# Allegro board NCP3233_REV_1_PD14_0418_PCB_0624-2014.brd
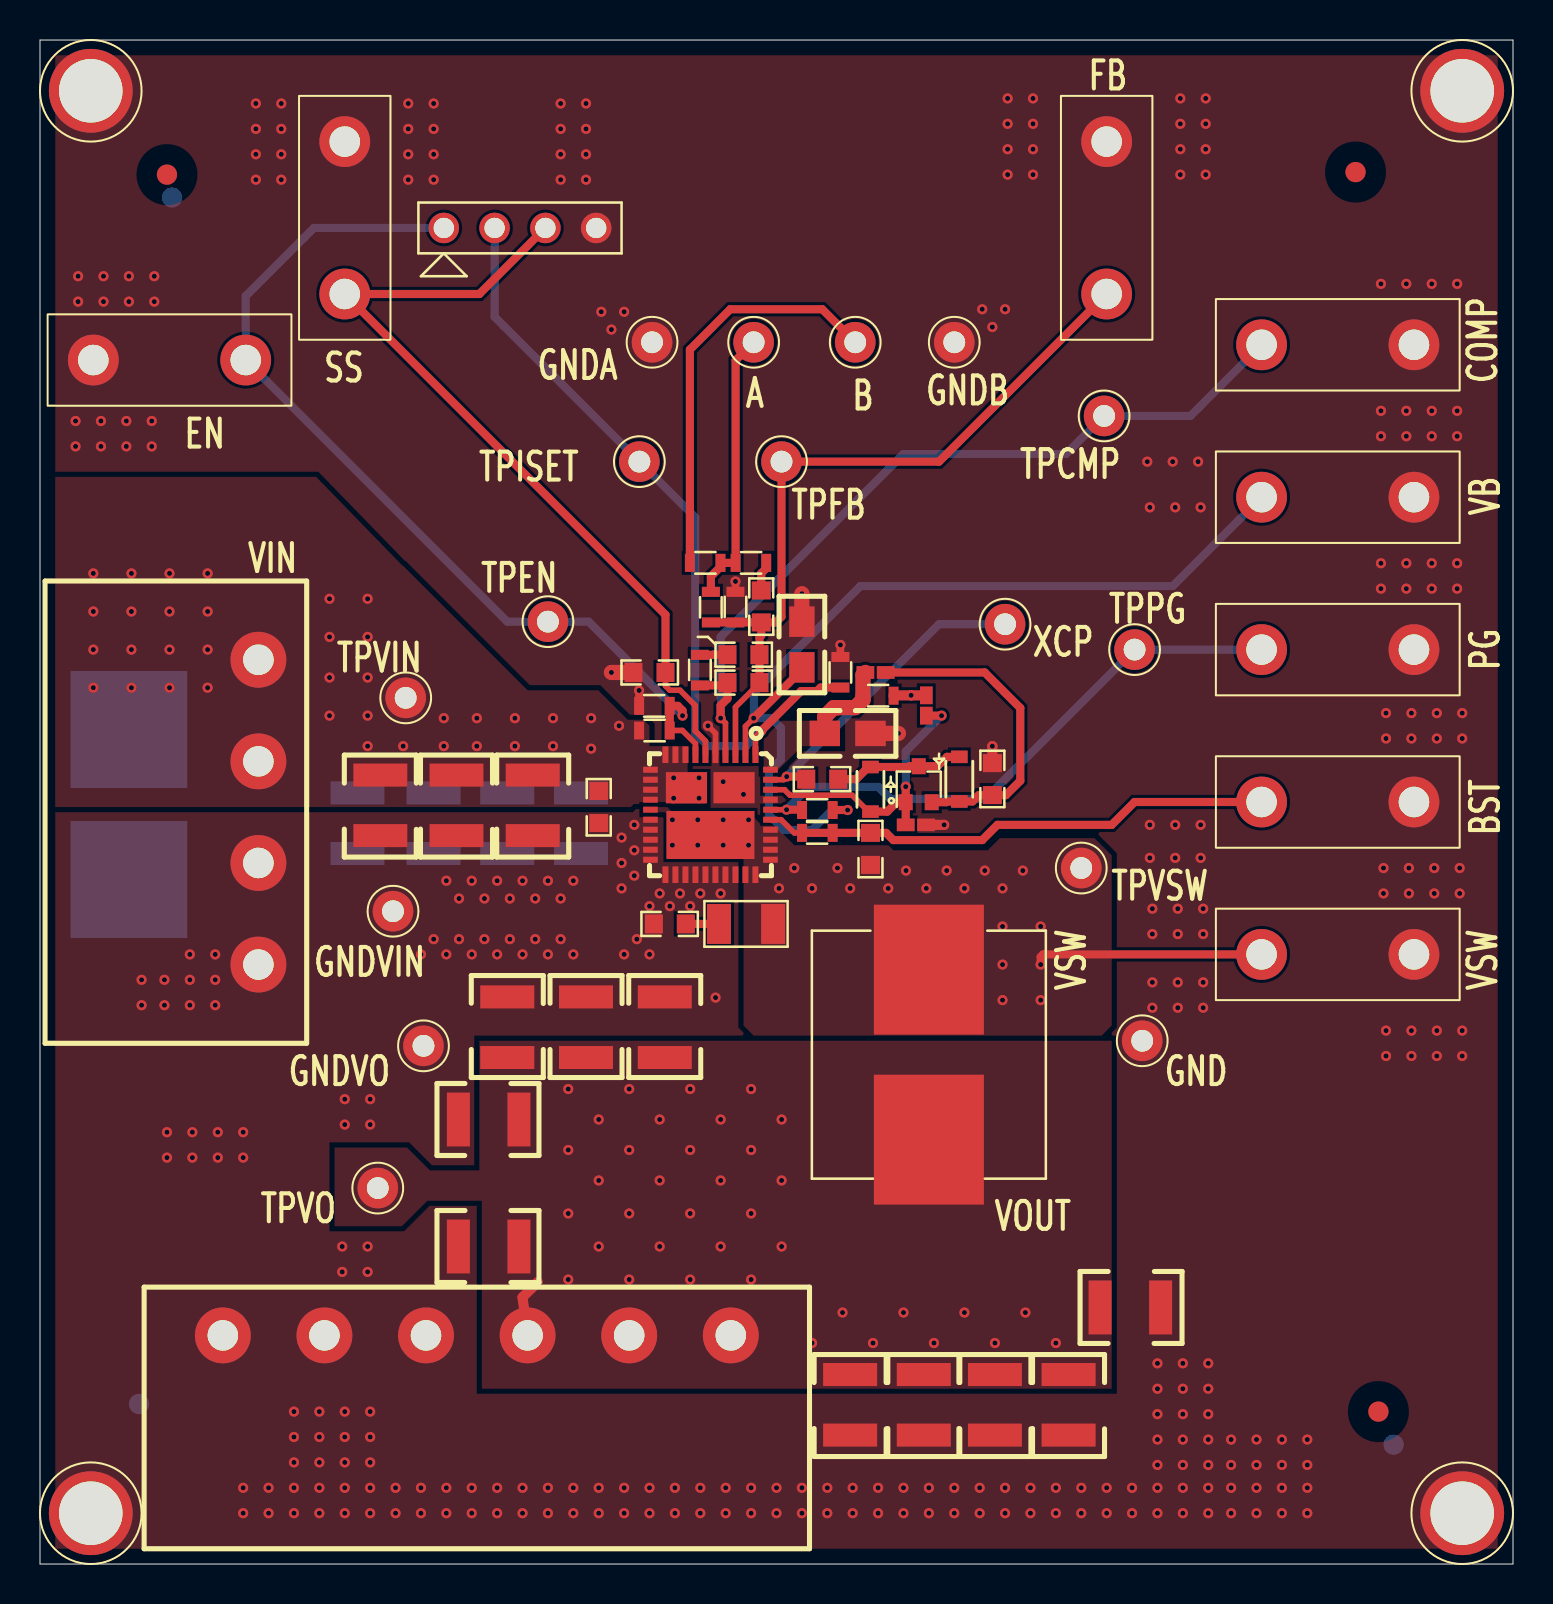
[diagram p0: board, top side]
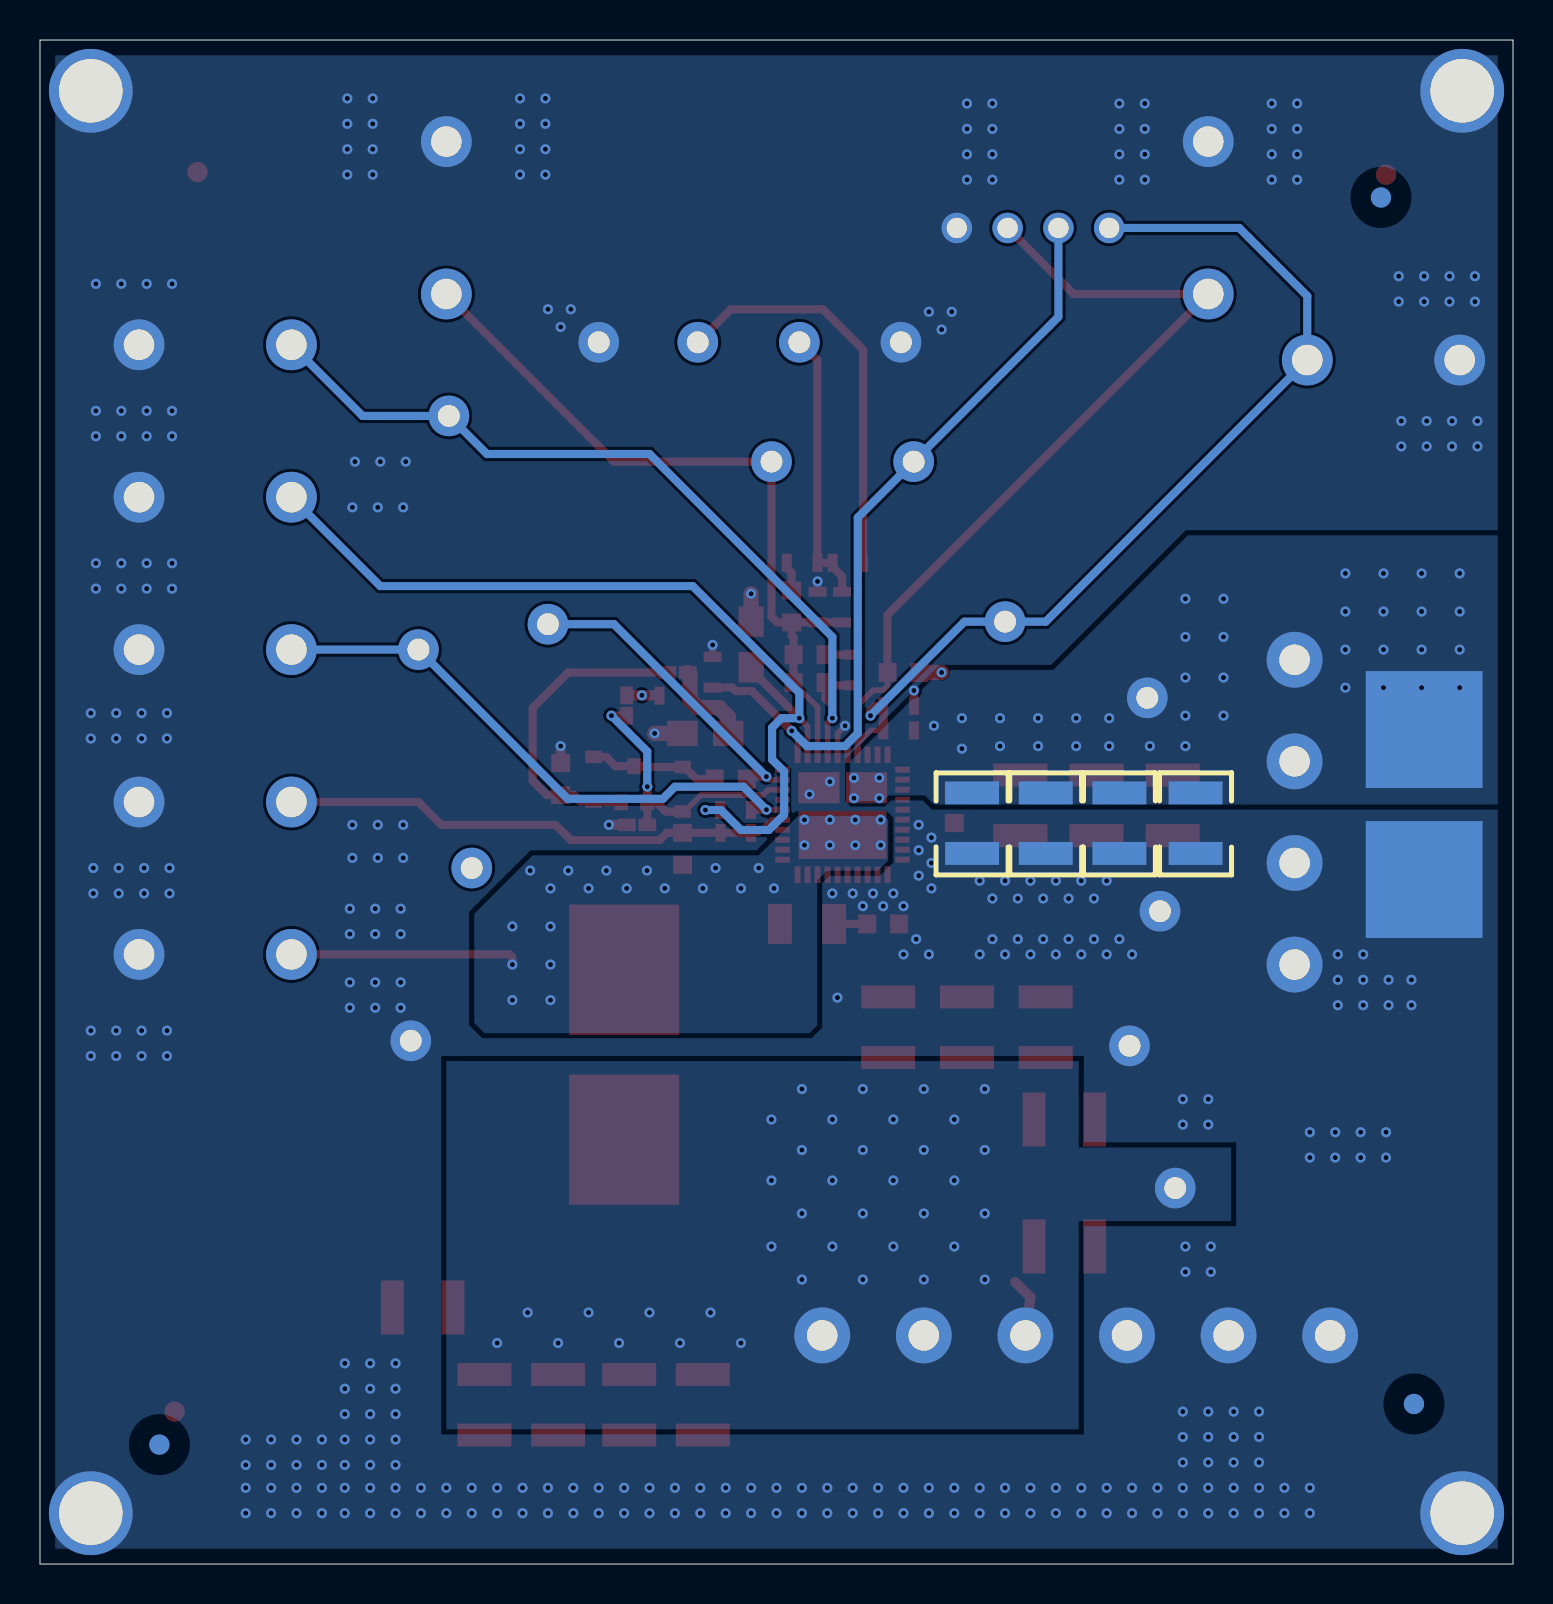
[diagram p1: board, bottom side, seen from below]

Outline 73.66 x 76.2 mm; copper layers: TOP, INNER LAYER 2, INNER LAYER 3, INNER LAYER 4, INNER LAYER 5, BOTTOM. Coordinates in mm from the lower left corner of the outline.
Outline path: 0,76.2 0,0 73.66,0 73.66,76.2 0,76.2

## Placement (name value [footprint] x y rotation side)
C1  22 uF  [C1210]  24.64 37.85 270 top
C2  22 uF  [C1210]  20.83 37.85 270 top
C3  22 uF  [C1210]  17.02 37.85 270 top
C4  22 uF  [C1210]  27.05 36.96 270 bottom
C5  22 uF  [C1210]  23.37 36.96 270 bottom
C6  1 uF  [C0603]  27.94 37.85 270 top
C7  22 uF  [C1210]  19.68 36.96 270 bottom
C8  22 nF  [C0603]  30.48 44.58 0 top
C9  0.1 uF  [C0603]  41.53 35.76 270 top
C10  4.7 uF  [C0805]  38.1 45.97 90 top
C11  1 uF  [C0805]  40.39 41.53 0 top
C13  DNP  [C0603]  31.5 32 180 top
C14  100 uF  [C1210]  31.24 26.92 90 top
C15  100 uF  [C1210]  27.3 26.92 90 top
C16  100 uF  [C1210]  23.37 26.92 90 top
C17  100 uF  [C1210]  22.35 22.23 180 top
C18  100 uF  [C1210]  22.35 15.88 180 top
C19  DNP  [C1210]  40.51 7.87 270 top
C20  DNP  [C1210]  44.2 7.87 270 top
C21  DNP  [C1210]  47.75 7.87 270 top
C22  DNP  [C1210]  51.44 7.87 270 top
C23  DNP  [C1210]  54.61 12.83 0 top
C24  10 pF  [C0603]  35.18 44.07 0 top
C25  2.2 nF  [C0603]  35.18 45.47 0 top
C26  680 pF  [C0603]  36.07 47.88 270 top
C27  22 uF  [C1210]  15.88 36.96 270 bottom
C28  1 uF  [C0603]  39.12 39.24 180 top
C29  1 uF  [C0603]  47.62 39.24 90 top
CBULK1  DNP  [SMD_E]  4.45 37.97 180 bottom
D1  NSR1020MW2  [SOD-323]  41.53 38.73 270 top
D2  NSR1020MW2  [SOD-323]  45.97 39.24 90 top
D3  BAT54SW  [SOT-323]  43.94 38.99 0 top
J1  HEADER 4  [HEADER_4P_200_RA]  10.92 29.97 90 top
J2  HEADER 6  [HEADER_6P_200_RA]  34.54 11.43 180 top
J3  TP_SCOPE  [SCOPE_SOCKET_PIN_300]  64.9 30.48 0 top
J4  TP_SCOPE  [SCOPE_SOCKET_PIN_300]  53.34 67.31 90 top
J7  TP_SCOPE  [SCOPE_SOCKET_PIN_300]  64.9 53.34 0 top
J8  TP_SCOPE  [SCOPE_SOCKET_PIN_300]  6.48 60.2 180 top
J9  TP_SCOPE  [SCOPE_SOCKET_PIN_300]  64.9 38.1 0 top
J11  TP_SCOPE  [SCOPE_SOCKET_PIN_300]  64.9 45.72 0 top
J12  TP_SCOPE  [SCOPE_SOCKET_PIN_300]  64.9 60.96 0 top
J13  TP_SCOPE  [SCOPE_SOCKET_PIN_300]  15.24 67.31 90 top
J14  CON4  [SIP-4]  20.19 66.8 0 top
JP1  SHORT_PIN  [SIG_ISO]  43.8 36.96 90 top
JP2  SHORT_PIN  [SIG_ISO]  44.32 42.93 0 top
JP3  SHORT_PIN  [SIG_ISO]  41.78 44.58 90 top
L1  0.47 uH  [MSS1278]  44.45 29.72 180 top
MTG1  Mounting Hole 0.125"  [P250H125]  2.54 2.54 0 top
MTG2  Mounting Hole 0.125"  [P250H125]  2.54 73.66 0 top
MTG3  Mounting Hole 0.125"  [P250H125]  71.12 2.54 0 top
MTG4  Mounting Hole 0.125"  [P250H125]  71.12 73.66 0 top
NOREF  -  []  0 0 0 top
NOREF#2  -  []  0 0 0 top
NOREF#3  -  []  0 76.2 0 top
NOREF#4  -  [unnamed#2]  6.35 69.47 0 top
NOREF#5  -  []  73.66 0 0 top
NOREF#6  -  [unnamed#2]  66.93 7.62 0 top
NOREF#7  -  [unnamed#2]  65.79 69.6 0 top
NOREF#8  -  [unnamed#2]  67.69 5.97 180 bottom
NOREF#9  -  [unnamed#2]  6.6 68.33 180 bottom
NOREF#10  -  [unnamed#2]  4.95 8 180 bottom
R1  20.0k  [R0603]  33.53 47.83 90 top
R2  30.1k  [R0603]  34.8 47.85 270 top
R3  7.87k  [R0603]  33.02 44.7 270 top
R4  1.00k  [R0603]  35.56 50.04 180 top
R7  DNP  [R0603]  30.73 41.66 180 top
R8  DNP  [R0603]  30.71 42.93 0 top
R9  10k  [R0603]  38.86 37.72 0 top
R10  5.11k  [R0603]  40.01 44.58 90 top
R11  DNP  [R0603]  38.86 36.58 0 top
R13  DNP  [R1206]  35.31 32 180 top
R14  0  [R0603]  41.91 43.43 0 top
RBODE1  0  [R0603]  33.27 50.04 180 top
TP1  A  [TP_100_43]  35.69 61.09 0 top
TP2  B  [TP_100_43]  40.77 61.09 0 top
TP3  GND  [TP_100_43]  55.12 26.16 0 top
TP4  GNDA  [TP_100_43]  30.61 61.09 0 top
TP5  GNDB  [TP_100_43]  45.72 61.09 0 top
TP6  GNDVIN  [TP_100_43]  17.65 32.64 0 top
TP7  GNDVO  [TP_100_43]  19.18 25.91 0 top
TP8  TPCMP  [TP_100_43]  53.21 57.4 0 top
TP9  TPEN  [TP_100_43]  25.4 47.12 0 top
TP10  TPFB  [TP_100_43]  37.08 55.12 0 top
TP11  TPISET  [TP_40MIL]  29.97 55.12 0 top
TP12  TPPG  [TP_100_43]  54.74 45.72 0 top
TP13  TPVIN  [TP_100_43]  18.29 43.31 0 top
TP14  TPVO  [TP_100_43]  16.89 18.8 0 top
TP15  TPVSW  [TP_100_43]  52.07 34.8 0 top
TP16  XCP  [TP_100_43]  48.26 46.99 0 top
U1  NCP3233  [QFN-40]  33.53 37.47 270 top

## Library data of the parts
C1-C11 C13-C24 C26-C29 = CAP NP_0
C25 = CAP NP_1
CBULK1 = CAP POL_0
D1 D2 = DIODE SCHOTTKY_1
D3 = Diode_Schottky_Dual_0
J1 = HEADER 4
J2 = HEADER 6
J3 J4 J7-J9 J11-J13 = CON2
J14 = CON4
JP1-JP3 = SHORT_PIN_SC_0
L1 = INDUCTOR_0
MTG1-MTG4 = Mounting Hole 0_0.125"
R1-R4 R7-R11 R13 R14 = RESISTOR_0
RBODE1 = RESISTOR_1
TP1-TP16 = TEST POINT
U1 = NCP3233_0

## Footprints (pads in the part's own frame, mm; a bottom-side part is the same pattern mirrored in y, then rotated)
C0603
  rect 0.9x0.95 smd: 1(-0.8,0) 2(0.799,0)
C0805
  rect 1.524x1.27 smd: 1(-1.143,0) 2(1.143,0)
C1210
  rect 1.15x2.7 smd: 1(-1.6,0) 2(1.429,0)
HEADER_4P_200_RA
  round 2.794 hole 1.524: 1(0,0) 2(5.08,0) 3(10.16,0) 4(15.24,0)
HEADER_6P_200_RA
  round 2.794 hole 1.524: 1(0,0) 2(5.08,0) 3(10.16,0) 4(15.24,0) 5(20.32,0) 6(25.4,0)
MSS1278
  rect 5.5x6.5 smd: 1(0,0) 2(0,8.5)
P250H125
  round 4.191 hole 3.175: 1(0,0)
QFN-40
  rect 0.83x0.3 smd: 1(-3,2.25) 2(-3,1.75) 3(-3,1.25) 4(-3,0.75) 5(-3,0.25) 6(-3,-0.25) 7(-3,-0.75) 8(-3,-1.25) 9(-3,-1.75) 10(-3,-2.25) 21(3,-2.25) 22(3,-1.75) 23(3,-1.25) 24(3,-0.75) 25(3,-0.25) 26(3,0.25) 27(3,0.75) 28(3,1.25) 29(3,1.75) 30(3,2.25)
  rect 0.3x0.73 smd: 11(-2.25,-3) 12(-1.75,-3) 13(-1.25,-3) 14(-0.75,-3) 15(-0.25,-3) 16(0.25,-3) 17(0.75,-3) 18(1.25,-3) 19(1.75,-3) 20(2.25,-3) 31(2.25,3) 32(1.75,3) 33(1.25,3) 34(0.75,3) 35(0.25,3) 36(-0.25,3) 37(-0.75,3) 38(-1.25,3) 39(-1.75,3) 40(-2.25,3)
  rect 1.56x2.06 smd: 41(-1.35,1.18) 42(-1.35,-1.2)
  rect 2.4x4.4 smd: 43(1.016,0)
R0603
  rect 0.5x0.9 smd: 1(-0.754,-0.02) 2(0.774,-0.02)
R1206
  rect 1.2x2 smd: 1(-1.354,0) 2(1.354,0)
SCOPE_SOCKET_PIN_300
  round 2.54 hole 1.524: 1(-3.81,0) 2(3.81,0)
SIG_ISO
  custom 0.159x0.159 smd: 1(0,0.508) 2(0,-0.508)
SIP-4
  round 1.524 hole 1.016: 1(0,0) 2(2.54,0) 3(5.08,0) 4(7.62,0)
SMD_E
  rect 5.842x5.842 smd: 1(0,3.75) 2(0,-3.75)
SOD-323
  rect 0.63x0.83 smd: 1(-1.115,0) 2(1.115,0)
SOT-323
  rect 0.7x0.8 smd: 1(-0.65,-0.9) 2(0.65,-0.9) 3(0,0.9)
TP_40MIL
  round 2.032 hole 1.092: 1(0,0)
TP_100_43
  round 2.032 hole 1.092: 1(0,0)
unnamed#2
  round 1.016 smd: (0,0)

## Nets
GND: C1.2 C2.2 C3.2 C4.2 C5.2 C6.2 C7.2 C8.1 C10.2 C11.2 C13.2 C14.2 C15.2 C16.2 C17.2 C18.2 C19.2 C20.2 C21.2 C22.2 C23.2 C27.2 C29.2 CBULK1.2 J1.1 J1.2 J2.4 J2.5 J2.6 J3.2 J4.2 J7.2 J8.2 J9.2 J11.2 J12.2 J13.2 J14.4 JP1.2 MTG1.1(GND1) MTG2.1(GND1) MTG3.1(GND1) MTG4.1(GND1) R2.1 R8.1 R10.2 TP3.1 TP4.1 TP5.1 TP6.1 TP7.1 U1.5(GND1) U1.16(PGND1) U1.17(PGND2) U1.18(PGND3) U1.19(PGND4) U1.20(PGND5) U1.21(PGND6) U1.22(PGND7) U1.23(PGND8) U1.24(PGND9) U1.25(PGND10) U1.26(PGND11) U1.27(PGND12) U1.28(PGND13) U1.37(GND2) U1.41(GND3)
VCC: C11.1 JP3.1 R14.1 U1.40(VCC)
VINX: D1.2(ANODE) D3.1(ANODE) JP1.1 JP2.2 U1.38(VINX)
$$$1198: C1.1 C2.1 C3.1 C4.1 C5.1 C6.1 C7.1 C27.1 CBULK1.1 J1.3 J1.4 JP2.1 R7.2 R14.2 TP13.1 U1.8(VIN1) U1.9(VIN2) U1.10(VIN3) U1.11(VIN4) U1.12(VIN5) U1.13(VIN6) U1.14(VIN7) U1.42(VIN8)
$$$9042: C13.1 R13.2
$$$10411: C26.1 R4.1
$$$10489: C25.1 R3.1
BST: C9.1 J9.1 R11.1 R11.2 U1.35(BST)
COMP: C24.1 J12.1 R3.2 TP8.1 U1.4(COMP)
EN: J8.1 J14.1 R7.1 R8.2 TP9.1 U1.7(EN)
FB: C24.2 C25.2 C26.2 J4.1 R1.1 R2.2 TP10.1 U1.3(FB)
ISET: J14.2 R10.1 TP11.1 U1.1(ISET)
PG: J11.1 R9.1 TP12.1 U1.36(PG)
SS: C8.2 J13.1 J14.3 U1.6(SS)
VB: C10.1 J7.1 R9.2 U1.2(VB)
VOUT: C14.1 C15.1 C16.1 C17.1 C18.1 C19.1 C20.1 C21.1 C22.1 C23.1 J2.1 J2.2 J2.3 L1.2 RBODE1.2 TP2.1 TP14.1
VSW: C9.2 J3.1 L1.1 R13.1 TP15.1 U1.15(VSW1) U1.29(VSW2) U1.30(VSW3) U1.31(VSW4) U1.32(VSW5) U1.33(VSW6) U1.34(VSW7) U1.43(VSW8)
XCP: C28.2 TP16.1 U1.39(XCP)
N12576: R1.2 R4.2 RBODE1.1 TP1.1
N42631: C28.1 D1.1(CATHODE) D2.2(ANODE) D3.3(COMMON)
N42647: C29.1 D2.1(CATHODE) D3.2(CATHODE) JP3.2

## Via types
v1: diameter 0.508, hole 0.254, TOP to BOTTOM, 444 vias

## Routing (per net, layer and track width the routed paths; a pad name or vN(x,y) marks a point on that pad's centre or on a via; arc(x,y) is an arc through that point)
GND: length 9.1
  TOP w0.279: v1(33.4,41.91) 33.78,41.53 U1.5
  TOP w0.381: R2.1 v1(34.78,49.13) ; R10.2 v1(40.03,45.95) ; R8.1 v1(29.96,43.68)
  TOP w0.508: JP1.2 v1(45.21,36.96) ; C29.2 v1(47.62,40.89)
  TOP w0.762: C8.1 v1(28.57,44.58) ; C11.2 v1(42.93,41.53) ; C10.2 v1(38.1,48.51)
  vias: v1(1.78,57.15) v1(1.78,55.88) v1(1.91,64.39) v1(1.91,63.12) v1(3.05,57.15) v1(3.05,55.88) v1(3.17,64.39) v1(3.17,63.12) v1(4.32,57.15) v1(4.32,55.88) v1(4.45,64.39) v1(4.45,63.12) v1(5.08,29.21) v1(5.08,27.94) v1(5.59,57.15) v1(5.59,55.88) v1(5.71,64.39) v1(5.71,63.12) v1(6.22,29.21) v1(6.22,27.94) v1(6.35,21.59) v1(6.35,20.32) v1(7.49,30.48) v1(7.49,29.21) v1(7.49,27.94) v1(7.62,21.59) v1(7.62,20.32) v1(8.76,30.48) v1(8.76,29.21) v1(8.76,27.94) v1(8.89,21.59) v1(8.89,20.32) v1(10.16,21.59) v1(10.16,20.32) v1(10.16,3.81) v1(10.16,2.54) v1(10.79,73.03) v1(10.79,71.75) v1(10.79,70.48) v1(10.79,69.22) v1(11.43,3.81) v1(11.43,2.54) v1(12.06,73.03) v1(12.06,71.75) v1(12.06,70.48) v1(12.06,69.22) v1(12.7,7.62) v1(12.7,6.35) v1(12.7,5.08) v1(12.7,3.81) v1(12.7,2.54) v1(13.97,7.62) v1(13.97,6.35) v1(13.97,5.08) v1(13.97,3.81) v1(13.97,2.54) v1(15.11,15.88) v1(15.11,14.61) v1(15.24,23.24) v1(15.24,21.97) v1(15.24,7.62) v1(15.24,6.35) v1(15.24,5.08) v1(15.24,3.81) v1(15.24,2.54) v1(16.38,15.88) v1(16.38,14.61) v1(16.51,23.24) v1(16.51,21.97) v1(16.51,7.62) v1(16.51,6.35) v1(16.51,5.08) v1(16.51,3.81) v1(16.51,2.54) v1(17.78,3.81) v1(17.78,2.54) v1(18.41,73.03) v1(18.41,71.75) v1(18.41,70.48) v1(18.41,69.22) v1(19.05,30.48) v1(19.05,3.81) v1(19.05,2.54) v1(19.68,73.03) v1(19.68,71.75) v1(19.68,70.48) v1(19.68,69.22) v1(19.68,31.24) v1(20.32,34.16) v1(20.32,30.48) v1(20.32,3.81) v1(20.32,2.54) v1(20.95,33.27) v1(20.95,31.24) v1(21.59,34.16) v1(21.59,30.48) v1(21.59,3.81) v1(21.59,2.54) v1(22.23,33.27) v1(22.23,31.24) v1(22.86,34.16) v1(22.86,30.48) v1(22.86,3.81) v1(22.86,2.54) v1(23.5,33.27) v1(23.5,31.24) v1(24.13,34.16) v1(24.13,30.48) v1(24.13,3.81) v1(24.13,2.54) v1(24.77,33.27) v1(24.77,31.24) v1(25.4,34.16) v1(25.4,30.48) v1(25.4,3.81) v1(25.4,2.54) v1(26.04,73.03) v1(26.04,71.75) v1(26.04,70.48) v1(26.04,69.22) v1(26.04,33.27) v1(26.04,31.24) v1(26.67,34.16) v1(26.67,30.48) v1(26.67,3.81) v1(26.67,2.54) v1(27.3,73.03) v1(27.3,71.75) v1(27.3,70.48) v1(27.3,69.22) v1(27.94,3.81) v1(27.94,2.54) v1(28.07,62.61) v1(28.57,61.72) v1(29.08,36.32) v1(29.08,35.05) v1(29.08,33.78) v1(29.21,62.61) v1(29.21,30.48) v1(29.21,3.81) v1(29.21,2.54) v1(29.72,36.96) v1(29.72,35.69) v1(29.72,34.42) v1(29.84,31.24) v1(30.48,32.89) v1(30.48,30.48) v1(30.48,3.81) v1(30.48,2.54) v1(30.99,33.53) v1(31.5,32.89) v1(31.75,3.81) v1(31.75,2.54) v1(32,33.53) v1(32.51,32.89) v1(33.02,33.53) v1(33.02,3.81) v1(33.02,2.54) v1(33.78,28.32) v1(34.04,33.53) v1(34.16,39.12) v1(34.29,3.81) v1(34.29,2.54) v1(35.18,38.48) v1(35.56,3.81) v1(35.56,2.54) v1(36.83,3.81) v1(36.83,2.54) v1(38.1,3.81) v1(38.1,2.54) v1(39.37,3.81) v1(39.37,2.54) v1(40.64,3.81) v1(40.64,2.54) v1(41.91,3.81) v1(41.91,2.54) v1(43.18,3.81) v1(43.18,2.54) v1(44.45,3.81) v1(44.45,2.54) v1(45.72,3.81) v1(45.72,2.54) v1(46.99,3.81) v1(46.99,2.54) v1(47.12,62.74) v1(47.62,61.85) v1(48.26,62.74) v1(48.26,3.81) v1(48.26,2.54) v1(48.39,73.28) v1(48.39,72.01) v1(48.39,70.74) v1(48.39,69.47) v1(49.53,3.81) v1(49.53,2.54) v1(49.66,73.28) v1(49.66,72.01) v1(49.66,70.74) v1(49.66,69.47) v1(50.8,3.81) v1(50.8,2.54) v1(52.07,3.81) v1(52.07,2.54) v1(53.34,3.81) v1(53.34,2.54) v1(54.61,3.81) v1(54.61,2.54) v1(55.37,55.12) v1(55.5,52.83) v1(55.5,36.96) v1(55.5,35.31) v1(55.63,32.77) v1(55.63,31.5) v1(55.63,29.08) v1(55.63,27.81) v1(55.88,10.03) v1(55.88,8.76) v1(55.88,7.49) v1(55.88,6.22) v1(55.88,4.95) v1(55.88,3.81) v1(55.88,2.54) v1(56.64,55.12) v1(56.77,52.83) v1(56.77,36.96) v1(56.77,35.31) v1(56.9,32.77) v1(56.9,31.5) v1(56.9,29.08) v1(56.9,27.81) v1(57.02,73.28) v1(57.02,72.01) v1(57.02,70.74) v1(57.02,69.47) v1(57.15,10.03) v1(57.15,8.76) v1(57.15,7.49) v1(57.15,6.22) v1(57.15,4.95) v1(57.15,3.81) v1(57.15,2.54) v1(57.91,55.12) v1(58.04,52.83) v1(58.04,36.96) v1(58.04,35.31) v1(58.17,32.77) v1(58.17,31.5) v1(58.17,29.08) v1(58.17,27.81) v1(58.29,73.28) v1(58.29,72.01) v1(58.29,70.74) v1(58.29,69.47) v1(58.42,10.03) v1(58.42,8.76) v1(58.42,7.49) v1(58.42,6.22) v1(58.42,4.95) v1(58.42,3.81) v1(58.42,2.54) v1(59.56,6.22) v1(59.56,4.95) v1(59.56,3.81) v1(59.56,2.54) v1(60.83,6.22) v1(60.83,4.95) v1(60.83,3.81) v1(60.83,2.54) v1(62.1,6.22) v1(62.1,4.95) v1(62.1,3.81) v1(62.1,2.54) v1(63.37,6.22) v1(63.37,4.95) v1(63.37,3.81) v1(63.37,2.54) v1(67.06,64.01) v1(67.06,57.66) v1(67.06,56.39) v1(67.06,50.04) v1(67.06,48.77) v1(67.18,34.8) v1(67.18,33.53) v1(67.31,42.55) v1(67.31,41.27) v1(67.31,26.67) v1(67.31,25.4) v1(68.33,64.01) v1(68.33,57.66) v1(68.33,56.39) v1(68.33,50.04) v1(68.33,48.77) v1(68.45,34.8) v1(68.45,33.53) v1(68.58,42.55) v1(68.58,41.27) v1(68.58,26.67) v1(68.58,25.4) v1(69.6,64.01) v1(69.6,57.66) v1(69.6,56.39) v1(69.6,50.04) v1(69.6,48.77) v1(69.72,34.8) v1(69.72,33.53) v1(69.85,42.55) v1(69.85,41.27) v1(69.85,26.67) v1(69.85,25.4) v1(70.87,64.01) v1(70.87,57.66) v1(70.87,56.39) v1(70.87,50.04) v1(70.87,48.77) v1(70.99,34.8) v1(70.99,33.53) v1(71.12,42.55) v1(71.12,41.27) v1(71.12,26.67) v1(71.12,25.4)
VCC: length 4.5
  TOP w0.762: JP3.1 41.16,44.46 R14.1 41.16,43.21 40.76,42.82 39.9,42.82 39.9,42.82 39.7,42.82 39.24,42.37 C11.1
VINX: length 14.4
  TOP w0.279: D1.2 41.43,37.62 40.61,38.44 37.5,38.44 37.23,38.71 U1.38
  TOP w0.406: v1(43.29,38.87) D3.1 ; D3.1 JP1.1 ; D3.1 42.84,38.09 42.37,37.62 D1.2 ; JP2.2 v1(45.09,42.42)
  BOTTOM w0.406: v1(43.29,38.87) 43.29,40.63 v1(45.09,42.42)
$$$1198: length 1.6
  TOP w0.508: R14.2 42.7,43.43 v1(43.56,43.43) JP2.1
  vias: v1(2.67,49.53) v1(2.67,47.62) v1(2.67,45.72) v1(2.67,43.81) v1(4.57,49.53) v1(4.57,47.62) v1(4.57,45.72) v1(4.57,43.81) v1(6.48,49.53) v1(6.48,47.62) v1(6.48,45.72) v1(6.48,43.81) v1(8.38,49.53) v1(8.38,47.62) v1(8.38,45.72) v1(8.38,43.81) v1(14.48,48.26) v1(14.48,46.35) v1(14.48,44.32) v1(14.48,42.42) v1(16.38,48.26) v1(16.38,46.35) v1(16.38,44.32) v1(16.38,42.42) v1(16.38,40.89) v1(18.16,40.89) v1(20.19,42.29) v1(20.19,40.89) v1(21.84,42.29) v1(21.84,40.89) v1(23.75,42.29) v1(23.75,40.89) v1(25.65,42.29) v1(25.65,40.89) v1(27.56,42.29) v1(27.56,40.77) v1(28.96,41.91) v1(31.69,39.31) v1(31.69,38.29) v1(32.96,39.31) v1(32.96,38.29)
$$$9042: length 1.7
  TOP w0.406: R13.2 C13.1
$$$10411: length 1.5
  TOP w0.406: R4.1 36.31,49.78 36.07,49.54 C26.1
$$$10489: length 1.4
  TOP w0.406: R3.1 33.65,45.46 33.66,45.47 C25.1
BST: length 25.8
  TOP w0.279: U1.35 37.06,37.22 37.72,36.56 R11.1
  TOP w0.406: J9.1 54.74,38.1 53.59,36.96 47.88,36.96 47.12,36.2 42.67,36.2 42.31,36.56 C9.1 R11.2 R11.1
COMP: length 42.4
  TOP w0.279: U1.4 34.28,42.05 v1(34.04,42.29)
  TOP w0.406: R3.2 34.24,43.93 C24.1 34.38,43.27 34.04,42.93 v1(34.04,42.29)
  BOTTOM w0.406: v1(34.04,42.29) 34.04,46.35 43.18,55.5 51.31,55.5 TP8.1 57.53,57.4 J12.1
EN: length 48.1
  TOP w0.279: R7.1 32.12,41.68 32.78,41.02 U1.7
  TOP w0.406: v1(32.13,42.42) 32.13,42.67 31.9,42.91 R8.2 R7.1
  BOTTOM w0.406: J14.1 13.69,66.8 13.2,66.31 10.29,63.4 J8.1 23.37,47.12 TP9.1 27.43,47.12 v1(32.13,42.42)
FB: length 38.3
  TOP w0.279: C24.2 35.98,44.04 34.78,42.84 U1.3
  TOP w0.406: J4.1 44.96,55.12 TP10.1 37.08,47.37 36.79,47.08 C26.2 ; C26.2 36.07,46.43 35.98,46.34 C25.2 C24.2 ; C26.2 R2.2 R1.1
ISET: length 39.5
  TOP w0.279: U1.1 35.78,41.37 v1(36.07,41.66)
  TOP w0.406: v1(36.07,41.66) 38.06,43.65 38.86,43.65 39.03,43.82 R10.1
  BOTTOM w0.406: J14.2 22.73,62.36 23.18,61.91 23.18,61.91 TP11.1 32.77,52.32 32.77,41.53 33.4,40.89 35.31,40.89 v1(36.07,41.66)
PG: length 29.2
  TOP w0.279: U1.36 v1(37.33,37.71)
  TOP w0.406: v1(37.33,37.71) 38.09,37.71 R9.1
  BOTTOM w0.406: J11.1 TP12.1 47.27,38.26 42.51,38.26 41.91,38.86 38.48,38.86 v1(37.33,37.71)
SS: length 42.2
  TOP w0.279: C8.2 31.28,43.9 31.5,43.69 32,43.69 32.77,42.93 32.77,41.66 33.28,41.14 U1.6
  TOP w0.406: C8.2 31.28,47.46 J13.1 21.97,63.5 25.27,66.8
VB: length 47.8
  TOP w0.279: v1(35.69,42.29) 35.28,41.88 U1.2
  TOP w0.406: 38.1,44.83 38.1,44.7 v1(35.69,42.29) ; R9.2 v1(40.39,37.7)
  BOTTOM w0.406: v1(40.39,37.7) 39.6,37.7 38.61,36.7 37.21,36.7 36.45,37.47 36.45,39.62 37.05,40.23 37.05,41.82 36.58,42.29 v1(35.69,42.29) 35.69,43.56 41.02,48.9 56.64,48.9 J7.1
VOUT: length 122.1
  TOP w0.406: RBODE1.2 32.5,60.72 34.52,62.74 39.12,62.74 TP2.1
  TOP w0.508: J2.3 24.13,13.34 24.89,14.1
  INNER LAYER 5 w0.406: TP2.1 46.1,66.42 69.72,66.42 71.88,64.26 71.88,23.37 66.17,17.65 51.05,17.65
  INNER LAYER 5 w0.508: 51.05,17.65 50.8,17.4
  vias: v1(26.42,23.75) v1(26.42,20.7) v1(26.42,17.53) v1(26.42,14.22) v1(27.94,22.23) v1(27.94,19.18) v1(27.94,15.88) v1(29.46,23.75) v1(29.46,20.7) v1(29.46,17.53) v1(29.46,14.22) v1(30.99,22.23) v1(30.99,19.18) v1(30.99,15.88) v1(32.51,23.75) v1(32.51,20.7) v1(32.51,17.53) v1(32.51,14.22) v1(34.04,22.23) v1(34.04,19.18) v1(34.04,15.88) v1(35.56,23.75) v1(35.56,20.7) v1(35.56,17.53) v1(35.56,14.22) v1(37.08,22.23) v1(37.08,19.18) v1(37.08,15.88) v1(38.61,11.05) v1(40.13,12.57) v1(41.66,11.05) v1(43.18,12.57) v1(44.7,11.05) v1(46.23,12.57) v1(47.75,11.05) v1(49.28,12.57) v1(50.8,11.05)
VSW: length 11.5
  TOP w0.406: v1(50.04,29.97) 50.04,30.35 50.16,30.48 J3.1
  vias: v1(31.62,37.21) v1(31.62,35.94) v1(32.89,37.21) v1(32.89,35.94) v1(34.16,37.21) v1(34.16,35.94) v1(35.43,37.21) v1(35.43,35.94) v1(36.96,33.78) v1(37.72,34.8) v1(38.61,33.78) v1(39.88,34.8) v1(40.51,33.78) v1(42.42,33.78) v1(43.31,34.67) v1(44.32,33.78) v1(45.34,34.67) v1(46.23,33.78) v1(47.24,34.67) v1(48.13,33.78) v1(48.13,31.88) v1(48.13,29.97) v1(48.13,28.19) v1(49.15,34.67) v1(50.04,31.88) v1(50.04,28.19)
XCP: length 16
  TOP w0.279: U1.39 37.18,39.22 v1(37.34,39.37)
  TOP w0.406: C28.2 38.19,39.37 v1(37.34,39.37)
  BOTTOM w0.406: v1(37.34,39.37) 44.96,46.99 TP16.1
N12576: length 13.8
  TOP w0.406: TP1.1 34.79,60.19 R4.2 RBODE1.1 34.03,49.86 33.55,49.38 R1.2
N42631: length 6.5
  TOP w0.406: D2.2 45.36,40.36 44.89,39.89 D3.3 43.49,39.89 43.45,39.85 D1.1 41.43,39.85 40.82,39.24 C28.1
N42647: length 16
  TOP w0.406: D3.2 45.32,38.09 45.36,38.13 D2.1 46.63,38.13 46.95,38.44 C29.1 48.3,38.44 49.02,39.16 49.02,42.8 47.24,44.58 JP3.2

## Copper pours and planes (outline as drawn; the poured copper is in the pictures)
GND on TOP: 0.76,0.76 0.76,75.44 72.9,75.44 72.9,0.76 ; 5 cut-outs
GND on BOTTOM: 0.76,0.76 0.76,75.44 72.9,75.44 72.9,0.76
GND on INNER LAYER 2, INNER LAYER 3, INNER LAYER 4: 0.76,75.44 72.9,75.44 72.9,0.76 0.76,0.76
GND on INNER LAYER 5: 0.76,0.76 0.76,37.47 24.38,37.47 24.38,43.94 16.38,51.94 0.76,51.94 0.76,75.44 72.9,75.44 72.9,0.76 ; 1 cut-out
VCC on TOP: 36.2,39.62 36.2,41.27 37.08,42.16 40.01,42.16 40.01,40.89 38.1,40.89 36.83,39.62
$$$1198 on TOP: 0.76,37.85 29.54,37.85 29.69,38 33.27,38 33.27,39.5 32.38,39.5 32.38,40.89 30.48,40.89 30.48,41.91 30.18,42.21 29.39,42.21 27.91,43.69 24.38,43.69 18.16,49.91 18.13,49.91 13.81,54.36 0.76,54.36
$$$1198 on BOTTOM: 0.76,51.44 0.76,37.97 28.96,37.97 29.41,38.43 31.22,38.43 31.52,38.13 33.02,38.13 33.15,38.25 33.15,40.13 28.57,44.7 22.99,44.7 16.26,51.44
$$$1198 on INNER LAYER 3: 21.21,44.58 21.21,39.37 27.81,39.37 28.7,38.23 33.15,38.23 33.4,38.48 33.4,40.13 35.81,40.13 35.81,38.99 36.2,38.61 46.86,38.61 46.86,47.24 41.78,47.24 41.78,45.34 41.02,44.58
$$$1198 on INNER LAYER 4: 21.08,44.96 21.08,38.99 28.57,38.99 29.34,38.1 33.15,38.1 33.4,38.35 33.4,40.13 35.81,40.13 35.81,38.99 36.2,38.61 46.74,38.61 46.74,47.37 41.53,47.37 41.53,45.21 41.15,44.96
$$$1198 on INNER LAYER 5: 0.76,51.31 0.76,37.85 24.26,37.85 24.26,43.81 16.76,51.31
VOUT on TOP: 53.59,26.16 21.97,26.16 21.97,19.68 19.49,19.68 18.35,20.83 14.73,20.83 14.73,16.89 18.1,16.89 19.37,18.16 22.1,18.16 22.1,8.76 53.59,8.76
VOUT on BOTTOM: 21.72,6.73 21.72,17.14 14.1,17.14 14.1,20.83 21.72,20.83 21.72,25.15 53.34,25.15 53.34,6.73
VOUT on INNER LAYER 5: 22.23,24.51 22.23,9.4 54.48,9.4 54.48,24.51
VSW on TOP: 35.69,26.42 35.18,26.92 35.18,35.31 35.05,35.43 31.62,35.43 31.5,35.56 31.5,37.34 31.24,37.59 30.23,37.59 30.23,37.85 31.37,37.85 31.75,37.47 35.56,37.47 36.07,36.96 36.83,36.96 36.96,36.83 36.96,36.7 37.72,35.94 42.42,35.94 42.67,35.69 47.4,35.69 48.01,36.3 52.73,36.3 53.59,35.43 53.59,26.92 53.09,26.42
VSW on BOTTOM: 51.44,26.54 51.94,27.05 51.94,32.51 49.02,35.43 37.72,35.43 35.76,37.39 31.42,37.39 31.24,37.21 31.24,35.18 31.75,34.67 34.29,34.67 34.8,34.16 34.8,26.92 35.18,26.54

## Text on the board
Ref Des/Silkscreen Top: EN | VIN | TPVO | GNDVO | GNDVIN | SS | TPVIN | TPISET | TPEN | GNDA | A | TPFB | B | GNDB | VOUT | TPCMP | XCP | FB | TPPG | TPVSW | GND | VSW | COMP | VB | PG | BST
DEVICE_TYPE_TOP: TOP
DIMENSION: INNER LAYER2
3: INNER LAYER3
User.5: INNER LAYER4
User.6: INNER LAYER5
User.7: BOTTOM
User.8: TOPSILK
User.9: TOPMASK
User.10: TOPPASTE
User.11: TOPASSEMBLY
User.12: BOTASSEMBLY
User.13: BOTMASK
User.14: BOTPASTE
User.15: BOTSILK
User.16: FAB
User.19: NCP3233_REV 1
User.21: FIGURE | SIZE | 10.0 | 40.0 | 43.0 | 60.0 | 125.0 | DRILL CHART: TOP to BOTTOM | ALL UNITS ARE IN MILS | TOLERANCE | +3.0/-10.0 | +3.0/-3.0 | +3.0/-0.0 | +2.0/-2.0 | PLATED | QTY | 444 | 4 | 16 | 26
User.22: SEE FAB NOTE 17 | SEE FAB NOTE 16 | DIMENSIONS ARE IN INCHES (MM) | INNER LAYER-2 | INNER LAYER-3 | INNER LAYER-4 | INNER LAYER-5 | LAYER STACKUP | BOTTOM | TOP | 6. SOLDER MASK COMPONENT SIDE AND SOLDER SIDE WITH LPI SOLDER MASK COLOR GREEN. | 7. IF ANY BGA EXISTS ON THE BOARD, PLUG VIAS FROM THE TOP SIDE WITH SOLDER MASK. | 8. FINISHED THICKNESS TO BE +/- .007 OR 10% WICHEVER IS GREATER. | 9. SILKSCREEN COMPONENT SIDE AND BOTTOM SIDE WITH WHITE NON-CONDUCTIVE EPOXY INK. | 10.FABRICATE PER DIMENTIONS SHOWN. | BOARD DIMENTION TOLERANCES .XX: +/-.01 .XXX:+/-.005 | 11.BREAK ALL SHARP EDGES. | 12.NO VENDOR LOGO OR NAME ON THE BOARD. | 15.CLIP SILKSCREEN UNDER NO MASK AREA. | 16.ALL VIAS IN THIS AREA NEEDS TO BE CONDUCTIVE FILLED. | 17.ALL VIAS IN THIS AREA NEEDS TO BE CONDUCTIVE FILLED. | 14.REMOVE UNUSED PADS IN ALL INNER LAYERS. | 13.WARP & TWIST SHALL NOT EXCEED 0.005 INCHES PER INCH. | 1. APPLICABLE STANDARDS / SPECIFICATIONS: | ANSI Y14.5-1982, DIMENTIONS AND TOLERANCES. | 2. COMPONENT SIDE SHOWN. | 3. MATERIAL: .O62 THK. FR4, NATURAL GREEN, UL94V-0 COMPLIANT, | START 1 OZ COPPER OUTER LAYERS. INNER LAYERS SHALL BE 1 OZ. | 4. HOLES TO BE PLATED THRU. PLATING IN HOLES TO BE .001" MIN. THICKNESS. | HOLE SIZES ARE AFTER PLATING.  HOLE TOLERANCE +/- .003 EXCEPT VIAS. | VIA TOLERANCE +.OOO -100% OF HOLE DIAMETER. | 5. FINISH: LEAD FREE GOLD FINISH. | NOTES: (UNLESS OTHERWISE SPECIFIED) | IT SHOULD BE SMOOTH AND FLAT ON TOP SIDE. | IT SHOULD BE SMOOTH AND FLAT ON BOTTOM SIDE. | LANDS AND EXPOSED PLATED AREA TO BE FREE OF INK.
